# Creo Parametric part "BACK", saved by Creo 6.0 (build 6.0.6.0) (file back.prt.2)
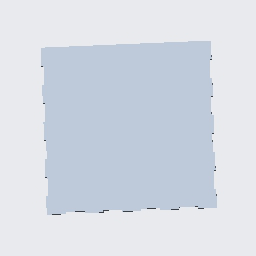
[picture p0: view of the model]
Units: Inch lbm Second (Pro/E Default); INCH, POUND, SECS

Created from: INLBS_PART_SOLID.PRT

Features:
  1. datum plane "RIGHT"
  2. datum plane "TOP"
  3. datum plane "FRONT"
  4. coordinate system
  5. sketch "Sketch 1"
  6. extrusion "Extrude 1"

Surfaces: 54 plane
